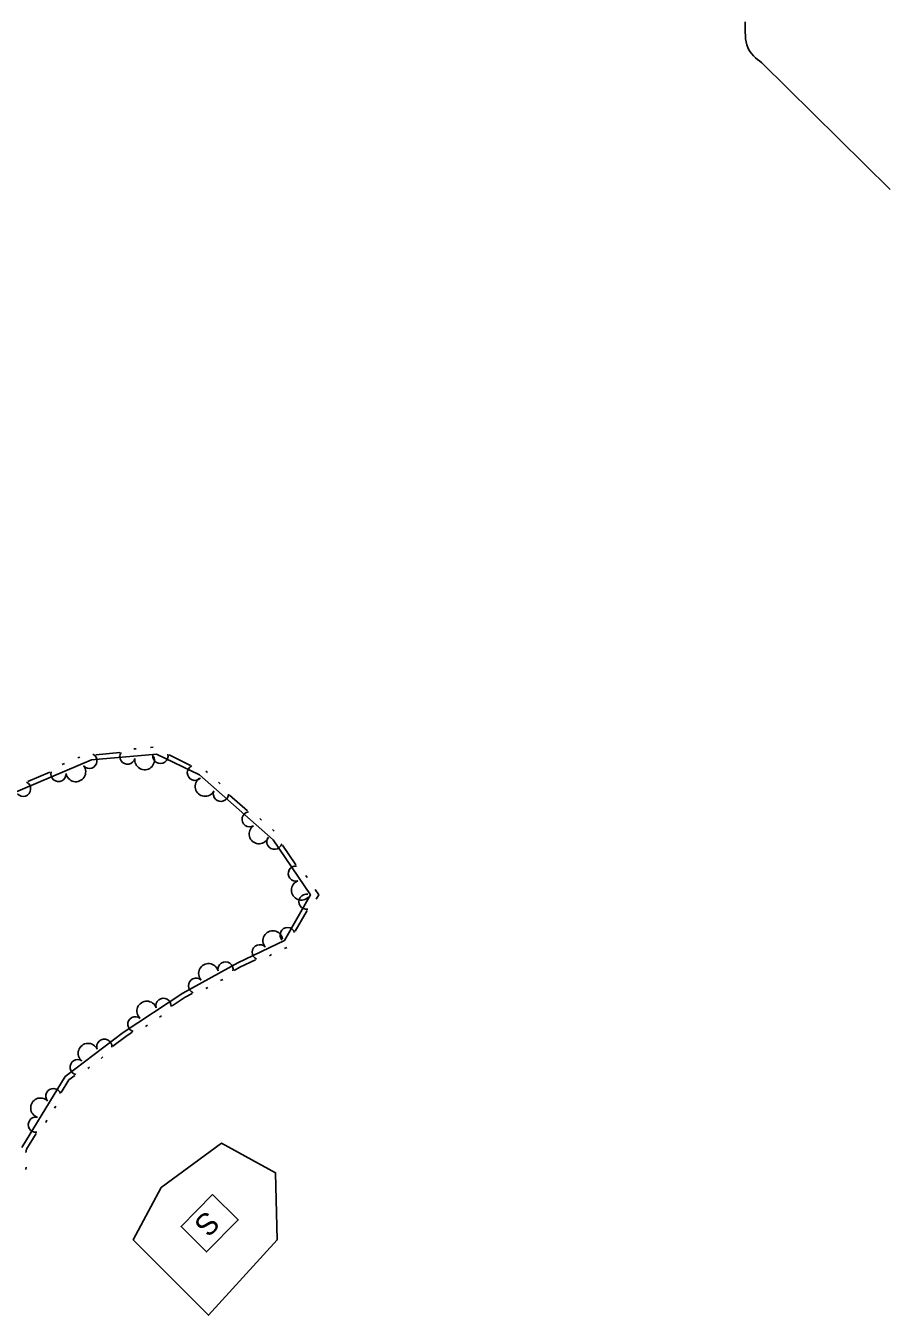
# Model space of a CAD drawing. Extents: x 2030130 to 2036320, y 723205 to 762423.
# Drawn here: x 2033597.2 to 2033745.1, y 761282.4 to 761502.9 of the extents above; entities that cross this region are included whole.
import ezdxf

# ---------------------------------------------------------------- set-up
doc = ezdxf.new("R2010")
doc.units = 0
for name, color, linetype in [('Draft_Station Tics Major', 7, 'Continuous'), ('Exist Terrain Model Ground Surface', 7, 'Continuous'), ('Old_Level_28', 7, 'Continuous'), ('Prop Alignment Horizontal', 7, 'Continuous')]:
    doc.layers.add(name, color=color, linetype=linetype)

msp = doc.modelspace()

# ---------------------------------------------------------------- linework, layer by layer
at = {"layer": 'Draft_Station Tics Major'}
for points in [[(2033592.47, 761370.59), (2033608.49, 761377.33), (2033619.59, 761378.35), (2033626.92, 761374.76), (2033639.54, 761363.65), (2033645.9, 761354.24), (2033641.48, 761346.47), (2033633.47, 761342.62), (2033624.09, 761337.47), (2033613.87, 761330.73), (2033604, 761323.17), (2033596.57, 761311.06)], [(2033606.12, 761377.67), (2033606.5, 761377.83)], [(2033609.23, 761378.22), (2033613.32, 761378.59)], [(2033615.73, 761379.23), (2033616.14, 761379.26)], [(2033618.59, 761379.49), (2033619, 761379.53)], [(2033621.73, 761378.22), (2033625.41, 761376.41)], [(2033603.48, 761376.55), (2033603.85, 761376.71)], [(2033628.02, 761375.44), (2033628.32, 761375.16)], [(2033597.59, 761373.63), (2033601.37, 761375.22)], [(2033630.17, 761373.54), (2033630.48, 761373.27)], [(2033632.06, 761371.33), (2033635.13, 761368.62)], [(2033637.25, 761367.3), (2033637.56, 761367.03)], [(2033639.41, 761365.41), (2033639.72, 761365.14)], [(2033641.12, 761362.78), (2033643.42, 761359.38)], [(2033645.13, 761357.57), (2033645.36, 761357.23)], [(2033646.74, 761355.19), (2033647.34, 761354.29), (2033646.92, 761353.54)], [(2033645.35, 761351.61), (2033643.32, 761348.05)], [(2033641.85, 761345.28), (2033641.48, 761345.11)], [(2033636.5, 761343.16), (2033633.85, 761341.89), (2033632.87, 761341.35)], [(2033639.26, 761344.04), (2033638.89, 761343.86)], [(2033628.39, 761338.43), (2033628.03, 761338.23)], [(2033630.91, 761339.81), (2033630.55, 761339.61)], [(2033625.68, 761337.41), (2033624.51, 761336.77), (2033622.25, 761335.28)], [(2033620.42, 761333.58), (2033620.08, 761333.35)], [(2033618.03, 761332), (2033617.69, 761331.77)], [(2033615.41, 761330.76), (2033614.35, 761330.06), (2033612.15, 761328.37)], [(2033608.16, 761324.81), (2033607.84, 761324.56)], [(2033610.44, 761326.55), (2033610.11, 761326.3)], [(2033605.63, 761323.39), (2033604.62, 761322.61), (2033603.3, 761320.46)], [(2033602.37, 761318.15), (2033602.15, 761317.8)], [(2033600.86, 761315.7), (2033600.65, 761315.35)], [(2033599.01, 761313.47), (2033597.35, 761310.77), (2033597.27, 761310.18)], [(2033620.36, 761304.21), (2033615.6, 761295.25), (2033628.48, 761282.37), (2033640.23, 761295.25), (2033639.95, 761306.73), (2033630.71, 761311.77), (2033620.36, 761304.21)], [(2033597.31, 761307.68), (2033597.25, 761307.28)]]:
    msp.add_lwpolyline(points, dxfattribs=at)
for centre, radius, start, end in [((2033608.11, 761377.17), 1.3, 221.2453, 62.0418), ((2033614.62, 761377.89), 1.3, 146.0072, 346.8038), ((2033617.55, 761377.34), 1.69, 171.2025, 19.2749), ((2033620.26, 761378.02), 1.3, 172.3699, 13.1665), ((2033605.79, 761375.3), 1.69, 188.7741, 36.8466), ((2033626.16, 761375.14), 1.3, 114.7035, 315.5), ((2033596.77, 761372.4), 1.3, 221.2453, 62.0418), ((2033602.82, 761374.94), 1.3, 163.5788, 4.3754), ((2033627.89, 761372.81), 1.69, 124.6033, 332.6758), ((2033630.59, 761371.53), 1.3, 157.0745, 357.8711), ((2033635.52, 761367.19), 1.3, 99.408, 300.2046), ((2033637.13, 761364.68), 1.69, 124.6033, 332.6758), ((2033639.75, 761363.34), 1.3, 142.4475, 343.2441), ((2033643.42, 761357.9), 1.3, 84.7811, 285.5776), ((2033644.35, 761355.06), 1.69, 109.9763, 318.0488), ((2033645.24, 761353.09), 1.3, 78.7892, 279.5858), ((2033639.48, 761346.42), 1.69, 11.6536, 219.7261), ((2033642, 761347.38), 1.3, 21.1228, 221.9193), ((2033637.25, 761344.44), 1.3, 44.1248, 244.9214), ((2033628.48, 761340.82), 1.69, 14.7232, 222.7957), ((2033631.39, 761341.48), 1.3, 349.5279, 190.3245), ((2033626.36, 761338.72), 1.3, 47.1944, 247.9909), ((2033617.93, 761334.39), 1.69, 19.3824, 227.4548), ((2033620.78, 761335.28), 1.3, 354.1871, 194.9836), ((2033615.98, 761332.12), 1.3, 51.8535, 252.6501), ((2033610.67, 761328.28), 1.3, 358.2048, 199.0013), ((2033607.89, 761327.18), 1.69, 23.4, 231.4725), ((2033606.11, 761324.79), 1.3, 55.8712, 256.6678), ((2033601.96, 761319.84), 1.3, 19.2411, 220.0377), ((2033599.76, 761317.83), 1.69, 44.4364, 252.5089), ((2033598.96, 761314.95), 1.3, 76.9076, 277.7042)]:
    msp.add_arc(centre, radius, start, end, dxfattribs=at)
at = {"layer": 'Exist Terrain Model Ground Surface'}
msp.add_lwpolyline([(2033629.18, 761303), (2033633.57, 761298.66), (2033628.16, 761293.19), (2033623.78, 761297.53)], close=True, dxfattribs=at)
at = {"layer": 'Prop Alignment Horizontal'}
msp.add_lwpolyline([(2033745.05, 761474.88), (2033723.11, 761496.53)], dxfattribs=at)
msp.add_spline([(2033720.25, 761503.57), (2033720.28, 761501.19), (2033720.68, 761499.18), (2033723.11, 761496.53)], degree=3, dxfattribs=at)

# ---------------------------------------------------------------- texts
at = {"layer": 'Old_Level_28'}
msp.add_text('S', height=3.69, rotation=224.9409, dxfattribs=at).set_placement((2033628.12, 761300.45))

doc.saveas('drawing.dxf')
